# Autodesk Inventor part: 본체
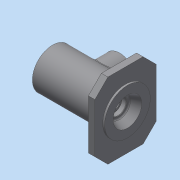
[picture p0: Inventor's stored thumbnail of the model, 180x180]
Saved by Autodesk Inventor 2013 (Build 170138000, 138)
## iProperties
Created: 2017-10
Part Number: 본체
Material: 일반
Document SubType Name: Modeling
Designer: dgall
Density: 1 g/cm^3
Author: dgall
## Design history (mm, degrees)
sketch "스케치1"
  geometry: L1 (-57.5, 0)-(57.5, 0); L2 (-57.5, 21)-(-57.5, 31); L3 (-57.5, 21)-(-48.5, 21); L4 (-48.5, 21)-(-48.5, 24); L5 (-48.5, 24)-(-45.5, 24); L6 (-45.5, 24)-(-45.5, 20); L7 (-45.5, 20)-(-36.5, 20); L8 (-36.5, 20)-(-36.5, 17.5); L9 (-36.5, 17.5)-(-33.25, 17.5); L10 (-33.25, 17.5)-(-33.25, 18.5); L11 (-33.25, 18.5)-(-31.5, 18.5); L12 (-31.5, 18.5)-(-31.5, 17.5); L13 (-31.5, 17.5)-(-20.5, 17.5); L14 (-20.5, 26)-(17.5, 26); L15 (17.5, 17.5)-(28.5, 17.5); L16 (28.5, 17.5)-(28.5, 16.5); L17 (28.5, 16.5)-(33.5, 16.5); L18 (33.5, 16.5)-(33.5, 10); L19 (33.5, 10)-(36.2, 10); L20 (36.2, 10)-(36.2, 12.5); L21 (36.2, 12.5)-(42.8, 12.5); L22 (42.8, 12.5)-(43.5, 12.904); L23 (43.5, 12.904)-(43.5, 16); L24 (43.5, 16)-(57.5, 22); L25 (-57.5, 31)-(44.5, 31); L26 (44.5, 31)-(44.5, 40); L27 (44.5, 40)-(54.5, 40); L28 (54.5, 40)-(54.5, 35); L29 (54.5, 35)-(57.5, 35); L30 (57.5, 35)-(57.5, 22); L31 (-20.5, 26)-(-20.5, 17.5); L32 (17.5, 26)-(17.5, 17.5); 3 further points
  constraints: 64 end point, 23 parallel, 6 perpendicular, 2 midpoint, 2 vertical alignment, 1 coincident, 1 horizontal
  dimensions: "d0" = 115 distance of L1.start L1.end; "d2" = 62 diameter of L25 L1; "d3" = 42 diameter of L3 L1; "d4" = 48 diameter of L5 L1; "d5" = 40 diameter of L7 L1; "d6" = 35 diameter of L9 L1; "d7" = 37 diameter of L11 L1; "d8" = 35 diameter of L13 L1; "d9" = 52 diameter of L14 L1; "d10" = 35 diameter of L15 L1; "d11" = 33 diameter of L17 L1; "d12" = 20 diameter of L18.end L1; "d13" = 25 diameter of L21 L1; "d14" = 30 deg angle of L21 L22; "d15" = 0.7 horizontal distance of L21.end L22.end; "d16" = 32 diameter of L23.end L1; "d17" = 44 diameter of L24.end L1; "d18" = 70 diameter of L29 L1; "d19" = 14 horizontal distance of L24.end L22.end; "d20" = 3 distance of L4.end L5.end; "d21" = 12 distance between parallel lines of L2 L6; "d22" = 21 horizontal distance of L2.start L7.end; "d23" = 1.75 distance of L10.end L11.end; "d24" = 26 horizontal distance of L2.start L12.end; "d25" = 38 distance of L14.start L14.end; "d26" = 60 horizontal distance of L15.end L11.end; "d29" = 7.3 horizontal distance of L19.end L22.end; "d30" = 2.7 distance of L18.end L19.end; "d31" = 3 distance of L28.end L29.end; "d32" = 10 distance of L26.end L27.end; "d33" = 80 diameter of L27 L1; "d34" = 11 distance of L12.end L13.end
revolve "회전1" sketch "스케치1" stored, may be unused: angle "d35" = 90 deg
sketch "스케치2"
  geometry: L1 (-58, 47)-(58, 47); L2 (58, 47)-(58, -47); L3 (58, -47)-(-58, -47); L4 (-58, -47)-(-58, 47); C1 r 35 at (0, 0) reference; C2 r 40 at (0, 0) reference; 2 further points
  constraints: 8 end point, 2 midpoint, 2 parallel, 1 horizontal, 1 horizontal alignment, 1 perpendicular, 1 vertical alignment
  dimensions: "d36" = 116 distance of L1.start L1.end; "d38" = 94 distance of L1.end L2.end
extrude "돌출1" join sketch "스케치2" distance "d39" = 10; taper "d40" = 0 deg
chamfer "모따기1" distance "d41" = 20; stored, may be unused: second distance "d42" = 2, angle "d43" = 45 deg
feature "스레드1" dims "d44" = 10, "d45" = 0
node "작업 평면1"
sketch "스케치3"
  geometry: L1 (57.5, 31)-(57.5, -31) reference; C1 r 25 at (1.5, 0); 1 further point
  constraints: 1 centre point, 1 horizontal alignment
  dimensions: "d47" = 50 diameter of C1; "d49" = 31 distance edge to line of C1 L1
extrude "돌출2" join sketch "스케치3" stored distance "d50" = 10; taper "d51" = 0 deg
sketch "스케치4"
  geometry: C1 r 25 at (0, 0) reference; 2 further points
  constraints: 1 coincident
hole "구멍1" sketch "스케치4" at (0, 0) diameter "d52" = 32; stored, may be unused: countersink angle "d56" = 90 deg, drill point angle "d58" = 0 deg; dims "d53" = 6, "d54" = 4, "d55" = 2, "d57" = 50
sketch "스케치5"
  geometry: C1 r 16 at (0, 0) reference; 3 further points
  constraints: 2 vertical alignment
  dimensions: "d59" = 20.5 distance of C1.centre point (0, -20.5); "d60" = 20.5 distance of point (0, 20.5) C1.centre (= d59)
hole "구멍2" sketch "스케치5" at (0, 20.5), (0, -20.5) diameter "d61" = 2.459; stored, may be unused: countersink angle "d65" = 82 deg, drill point angle "d67" = 118 deg; dims "d62" = 6, "d63" = 3.023, "d64" = 2, "d66" = 8
fillet "모깎기1" dims "d68" = 0.3
fillet "모깎기2" dims "d69" = 0.3
fillet "모깎기3" dims "d70" = 3
fillet "모깎기4" dims "d71" = 3
fillet "모깎기5" dims "d72" = 3
chamfer "모따기2" distance "d73" = 1; stored, may be unused: second distance "d74" = 2, angle "d75" = 45 deg
chamfer "모따기3" distance "d76" = 1; stored, may be unused: second distance "d77" = 2, angle "d78" = 45 deg
fillet "모깎기6" dims "d79" = 3
node "솔리드1"
other parameters: "d46" = 47
